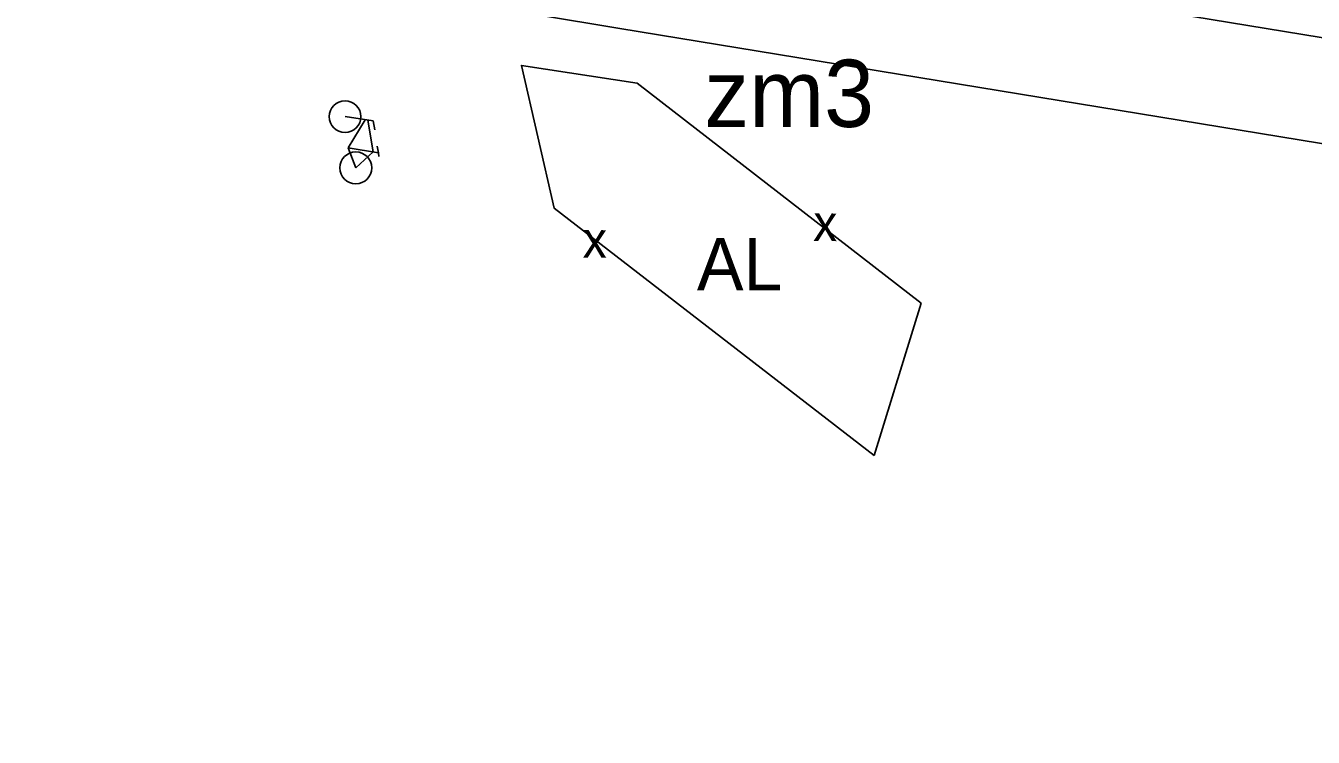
# Model space of a CAD drawing. Extents: x -555070 to -553076, y -1186731 to -1182766.
# Drawn here: x -554414.1 to -554069.4, y -1185758.1 to -1185567.7 of the extents above; entities that cross this region are included whole.
import ezdxf

# ---------------------------------------------------------------- set-up
doc = ezdxf.new("R2010")
doc.units = 0
for name, color, linetype in [('Level 10', 7, 'Continuous'), ('Level 29', 7, 'Continuous'), ('Level 58', 7, 'Continuous'), ('Level 59', 7, 'Continuous'), ('OBRYS_PLOCH', 7, 'Continuous'), ('stav_AL', 7, 'Continuous'), ('ZRUSENE_PLOCHY', 7, 'Continuous')]:
    doc.layers.add(name, color=color, linetype=linetype)

msp = doc.modelspace()

# ---------------------------------------------------------------- linework, layer by layer
at = {"layer": 'Level 29'}
msp.add_line((-554277.11, -1185564.77), (-554255.09, -1185568.38), dxfattribs=at)
for points in [[(-555065.37, -1185337.55), (-554878.61, -1185437.76), (-554591.7, -1185484.82), (-554218.96, -1185545.93), (-553901.49, -1185597.94), (-553620.76, -1185643.99), (-553313.81, -1185694.25), (-553085.95, -1185731.63)], [(-554255.09, -1185568.38), (-554255.09, -1185568.38), (-554223.49, -1185573.56), (-553906.02, -1185625.57), (-553625.29, -1185671.62), (-553318.33, -1185721.88), (-553097.68, -1185758.08)]]:
    msp.add_lwpolyline(points, dxfattribs=at)
at = {"layer": 'Level 58'}
for p, q in [((-554328.64, -1185591.99), (-554321.09, -1185593.13)), ((-554327.83, -1185600.33), (-554323.28, -1185592.8)), ((-554322.57, -1185592.9), (-554321.09, -1185601.43)), ((-554321.09, -1185593.13), (-554320.64, -1185595.53)), ((-554319.73, -1185601.65), (-554320.08, -1185599.87)), ((-554319.73, -1185601.65), (-554327.83, -1185600.33)), ((-554327.83, -1185600.33), (-554325.77, -1185605.69)), ((-554325.77, -1185605.69), (-554321.09, -1185601.43)), ((-554319.73, -1185601.65), (-554319.57, -1185602.63))]:
    msp.add_line(p, q, dxfattribs=at)
for centre in [(-554328.64, -1185591.99), (-554325.77, -1185605.69)]:
    msp.add_circle(centre, 4.25, dxfattribs=at)
at = {"layer": 'OBRYS_PLOCH'}
msp.add_line((-554187.01, -1185682.72), (-554174.43, -1185641.89), dxfattribs=at)
msp.add_lwpolyline([(-554174.43, -1185641.89), (-554250.48, -1185583.07), (-554281.41, -1185578.27), (-554272.65, -1185616.49), (-554187.01, -1185682.72)], dxfattribs=at)
at = {"layer": 'stav_AL'}
msp.add_line((-554187.01, -1185682.72), (-554174.43, -1185641.89), dxfattribs=at)
msp.add_lwpolyline([(-554174.43, -1185641.89), (-554250.48, -1185583.07), (-554281.41, -1185578.27), (-554272.65, -1185616.49), (-554187.01, -1185682.72)], dxfattribs=at)
at = {"layer": 'ZRUSENE_PLOCHY'}
msp.add_line((-554187.01, -1185682.72), (-554174.43, -1185641.89), dxfattribs=at)
msp.add_lwpolyline([(-554174.43, -1185641.89), (-554250.48, -1185583.07), (-554281.41, -1185578.27), (-554272.65, -1185616.49), (-554187.01, -1185682.72)], dxfattribs=at)

# ---------------------------------------------------------------- texts
at = {"layer": 'Level 10'}
msp.add_text('zm3', height=18, dxfattribs=at).set_placement((-554232.47, -1185594.75))
at = {"layer": 'Level 59'}
msp.add_text('AL', height=14, dxfattribs=at).set_placement((-554234.44, -1185638.47))
at = {"layer": 'ZRUSENE_PLOCHY'}
for p in [(-554203.33, -1185625.24), (-554265.02, -1185629.7)]:
    msp.add_text('x', height=9.63, rotation=359.2857, dxfattribs=at).set_placement(p)

doc.saveas('drawing.dxf')
